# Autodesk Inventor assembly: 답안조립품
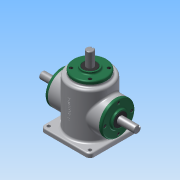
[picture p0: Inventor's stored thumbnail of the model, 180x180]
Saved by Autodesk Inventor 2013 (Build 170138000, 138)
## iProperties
Created: 2015-10
Part Number: 답안조립품
Document SubType Name: Assembly
Designer: semtle
Author: semtle
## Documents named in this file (14)
- C:\Users\semtle\Desktop\451007V1009\답안조립품.iam
- C:\Users\semtle\Desktop\451007V1009\1-본체.ipt
- C:\Users\semtle\Desktop\451007V1009\커버.ipt
- C:\Users\semtle\Desktop\451007V1009\베어링 6203.ipt
- C:\Users\semtle\Desktop\451007V1009\오일실.ipt
- C:\Users\semtle\Desktop\451007V1009\메인 축.ipt
- 메인 축.ipt
- C:\Users\semtle\Desktop\451007V1009\키 5x5.ipt
- C:\Users\semtle\Desktop\451007V1009\서브 축.ipt
- 서브 축.ipt
- C:\Users\semtle\Desktop\451007V1009\키 4x4.ipt
- C:\Users\semtle\Desktop\451007V1009\메인 베벨기어.ipt
- C:\Users\semtle\Desktop\451007V1009\서브 베벨기어.ipt
- C:\Users\semtle\Desktop\451007V1009\M4.ipt
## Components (13 placed, 2 different names)
1. 1-본체:1
2. M4:1
3. M4:2
4. M4:3
5. M4:4
6. M4:5
7. M4:6
8. M4:7
9. M4:8
10. M4:9
11. M4:10
12. M4:11
13. M4:12
